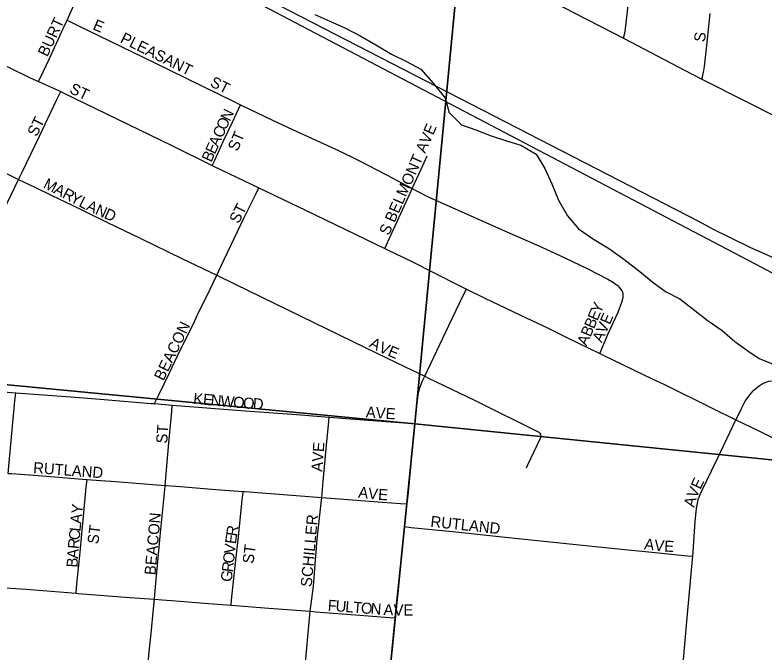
# Model space of a CAD drawing. Extents: x -209 to 4852, y 0 to 905.
# Drawn here: x 140.68 to 153.48, y 247.81 to 258.69 of the extents above; entities that cross this region are included whole.
import ezdxf

# ---------------------------------------------------------------- set-up
doc = ezdxf.new("R2010")
doc.units = 0
for name, color, linetype in [('GM_X_Airport_Location_Class_2', 7, 'Continuous'), ('GM_X_Airport_Location_Class_3', 7, 'Continuous'), ('GM_X_County_Road', 7, 'Continuous'), ('GM_X_Minor_River', 7, 'Continuous'), ('GM_X_US_Route', 7, 'Continuous')]:
    doc.layers.add(name, color=color, linetype=linetype)

msp = doc.modelspace()

# ---------------------------------------------------------------- linework, layer by layer
at = {"layer": 'GM_X_Airport_Location_Class_2'}
for points in [[(141.572, 258.596), (141.712, 258.903), (142.113, 259.746), (142.271, 260.083), (142.485, 260.53), (142.766, 261.143), (143.078, 261.826), (143.253, 262.232), (143.279, 262.293)], [(149.963, 258.863), (150.214, 258.736), (150.91, 258.379), (151.076, 258.293)], [(151.076, 258.293), (151.093, 258.351), (151.106, 258.41), (151.113, 258.453), (151.156, 258.85)], [(152.416, 257.593), (152.425, 257.631), (152.451, 257.738), (152.463, 257.808), (152.5, 258.163), (152.556, 258.713)], [(141.087, 257.55), (141.173, 257.727), (141.27, 257.944), (141.508, 258.457), (141.572, 258.596)], [(141.572, 258.596), (141.678, 258.547), (141.735, 258.521), (143.074, 257.869), (144.412, 257.215), (144.536, 257.154)], [(151.076, 258.293), (152.24, 257.682), (152.416, 257.593)], [(140.15, 258.002), (140.943, 257.616), (141.087, 257.55)], [(141.087, 257.55), (141.465, 257.38)], [(152.416, 257.593), (153.161, 257.216), (153.667, 256.96)], [(140.746, 255.878), (140.805, 256.002), (141.101, 256.618), (141.395, 257.234), (141.465, 257.38)], [(141.465, 257.38), (141.508, 257.36), (143.352, 256.463), (144.051, 256.116)], [(144.051, 256.116), (144.094, 256.208), (144.253, 256.548), (144.39, 256.843), (144.536, 257.154)], [(144.536, 257.154), (145.082, 256.89), (145.423, 256.733), (146.209, 256.374), (146.543, 256.209), (147.038, 255.951), (147.468, 255.722)], [(139.444, 256.51), (139.801, 256.339), (140.358, 256.065), (140.638, 255.93), (140.746, 255.878)], [(147.468, 255.722), (147.62, 256.052), (147.725, 256.279)], [(144.051, 256.116), (144.075, 256.104), (144.469, 255.918), (144.85, 255.736)], [(140.085, 254.51), (140.332, 255.023), (140.381, 255.13), (140.485, 255.34), (140.618, 255.613), (140.746, 255.878)], [(140.746, 255.878), (141.031, 255.742), (141.312, 255.607), (141.647, 255.444), (141.872, 255.337), (142.262, 255.146), (142.821, 254.874), (143.547, 254.523), (144.131, 254.242)], [(144.131, 254.242), (144.202, 254.391), (144.6, 255.226), (144.792, 255.617), (144.85, 255.736)], [(144.85, 255.736), (145.647, 255.356), (146.998, 254.699)], [(146.998, 254.699), (147.028, 254.763), (147.08, 254.875), (147.433, 255.646), (147.468, 255.722)], [(147.468, 255.722), (147.531, 255.688), (147.753, 255.578), (148.148, 255.398), (148.942, 255.046), (149.68, 254.721), (150.074, 254.54), (150.466, 254.353), (150.797, 254.183), (150.807, 254.178), (150.904, 254.121), (150.929, 254.104), (150.954, 254.085), (150.979, 254.066), (151.002, 254.044)], [(146.998, 254.699), (147.044, 254.677), (147.436, 254.487), (148.269, 254.068), (148.393, 254.006)], [(143.065, 252.051), (143.077, 252.074), (143.14, 252.199), (143.321, 252.577), (143.506, 252.964), (143.726, 253.403), (143.803, 253.566), (144.015, 254.004), (144.131, 254.242)], [(144.131, 254.242), (144.445, 254.092), (145.341, 253.654), (146.455, 253.11), (146.85, 252.918), (147.348, 252.679), (147.681, 252.519)], [(147.681, 252.519), (148.094, 253.387), (148.345, 253.906), (148.393, 254.006)], [(148.393, 254.006), (148.709, 253.85), (149.414, 253.516), (149.78, 253.343), (150.107, 253.181), (150.67, 252.906)], [(150.67, 252.906), (150.705, 252.987), (150.805, 253.22), (150.907, 253.443), (150.984, 253.615), (151.048, 253.785), (151.058, 253.818), (151.066, 253.843), (151.07, 253.865), (151.07, 253.875), (151.072, 253.886), (151.072, 253.901), (151.07, 253.926), (151.063, 253.953), (151.052, 253.979), (151.038, 254.002), (151.028, 254.017), (151.002, 254.044)], [(150.67, 252.906), (150.728, 252.878), (151.58, 252.468), (151.777, 252.376), (152.603, 251.968), (152.998, 251.774)], [(147.517, 251.705), (147.548, 252.012), (147.569, 252.198), (147.581, 252.257), (147.599, 252.322), (147.642, 252.438), (147.681, 252.519)], [(147.681, 252.519), (147.747, 252.487), (148.532, 252.108), (149.629, 251.563), (149.635, 251.559), (149.639, 251.556), (149.65, 251.547), (149.662, 251.528)], [(152.998, 251.774), (153.039, 251.859), (153.092, 251.969), (153.148, 252.079), (153.181, 252.13), (153.257, 252.227), (153.299, 252.272), (153.344, 252.314), (153.393, 252.352), (153.444, 252.386), (153.499, 252.414), (153.557, 252.433), (153.618, 252.441), (153.679, 252.438), (153.74, 252.43)], [(139.052, 252.363), (139.608, 252.32), (140.696, 252.237)], [(140.566, 250.86), (140.683, 252.099), (140.696, 252.237)], [(140.696, 252.237), (141.093, 252.207), (141.713, 252.159), (142.208, 252.119), (143.012, 252.055), (143.065, 252.051)], [(143.065, 252.051), (143.37, 252.027)], [(143.246, 250.655), (143.31, 251.383), (143.354, 251.855), (143.368, 252.006), (143.37, 252.027)], [(143.37, 252.027), (144.622, 251.93), (145.489, 251.866), (146.051, 251.82)], [(145.922, 250.448), (145.947, 250.722), (146.004, 251.341), (146.04, 251.689), (146.051, 251.82)], [(146.051, 251.82), (146.416, 251.79), (147.406, 251.714), (147.517, 251.705)], [(147.381, 250.338), (147.402, 250.532), (147.486, 251.399), (147.517, 251.705)], [(152.259, 249.445), (152.264, 249.514), (152.302, 250.044), (152.323, 250.255), (152.339, 250.35), (152.347, 250.386), (152.354, 250.413), (152.386, 250.5), (152.414, 250.563), (152.578, 250.903), (152.686, 251.125), (152.998, 251.774)], [(152.998, 251.774), (153.376, 251.589), (154.044, 251.262), (154.213, 251.184), (154.371, 251.114), (154.536, 251.038), (154.866, 250.875), (155.14, 250.74), (155.248, 250.689), (155.364, 250.632), (155.622, 250.506), (155.907, 250.366), (156.119, 250.263), (156.505, 250.077), (156.901, 249.887), (157.469, 249.616), (157.942, 249.381), (158.095, 249.304)], [(149.418, 250.953), (149.445, 251.006), (149.659, 251.459), (149.662, 251.466), (149.665, 251.473), (149.667, 251.482), (149.669, 251.499), (149.662, 251.528)], [(140.566, 250.86), (140.577, 250.859), (140.626, 250.856), (141.007, 250.828), (141.366, 250.799), (141.903, 250.756), (141.914, 250.755)], [(141.728, 248.812), (141.729, 248.823), (141.742, 248.965), (141.795, 249.515), (141.852, 250.131), (141.901, 250.622), (141.914, 250.755)], [(141.914, 250.755), (142.145, 250.738), (142.325, 250.724), (142.686, 250.699), (143.246, 250.655)], [(143.065, 248.71), (143.08, 248.859), (143.164, 249.785), (143.24, 250.585), (143.246, 250.655)], [(143.246, 250.655), (143.274, 250.653), (143.508, 250.634), (144.114, 250.586), (144.579, 250.551)], [(144.373, 248.608), (144.375, 248.629), (144.388, 248.75), (144.458, 249.384), (144.494, 249.726), (144.565, 250.402), (144.578, 250.538), (144.579, 250.551)], [(144.579, 250.551), (144.607, 250.549), (145.412, 250.488), (145.922, 250.448)], [(145.725, 248.504), (145.78, 248.93), (145.808, 249.301), (145.844, 249.734), (145.913, 250.351), (145.922, 250.448)], [(145.922, 250.448), (146.154, 250.43), (146.958, 250.368), (147.267, 250.346), (147.381, 250.338)], [(147.339, 249.95), (147.381, 250.338)], [(147.176, 248.393), (147.187, 248.51), (147.295, 249.55), (147.339, 249.95)], [(147.339, 249.95), (147.452, 249.938), (148.211, 249.86), (148.894, 249.789), (149.388, 249.736), (149.883, 249.685), (150.872, 249.583), (151.677, 249.503), (152.172, 249.453), (152.259, 249.445)], [(152.003, 246.542), (152.008, 246.598), (152.021, 246.764), (152.055, 247.156), (152.16, 248.33), (152.24, 249.204), (152.259, 249.445)], [(140.384, 248.918), (140.521, 248.905), (140.874, 248.88), (141.728, 248.812)], [(141.728, 248.812), (141.762, 248.809), (142.646, 248.739), (143.065, 248.71)], [(142.935, 247.375), (142.947, 247.502), (142.976, 247.811), (143.013, 248.181), (143.043, 248.489), (143.065, 248.71)], [(143.065, 248.71), (143.197, 248.7), (143.503, 248.676), (143.99, 248.637), (144.373, 248.608)], [(144.373, 248.608), (145.017, 248.558), (145.725, 248.504)], [(145.605, 247.164), (145.614, 247.263), (145.677, 248.003), (145.725, 248.504)], [(145.725, 248.504), (145.821, 248.497), (146.5, 248.443), (147.082, 248.4), (147.176, 248.393)], [(147.05, 247.048), (147.052, 247.072), (147.063, 247.186), (147.094, 247.522), (147.176, 248.393)]]:
    msp.add_lwpolyline(points, dxfattribs=at)
at = {"layer": 'GM_X_County_Road'}
for points in [[(145.805, 258.695), (146.062, 258.58), (146.326, 258.464), (146.589, 258.325), (146.845, 258.179), (147.117, 258.018), (147.373, 257.895), (147.614, 257.764), (147.824, 257.52), (148.034, 257.26), (148.093, 257.025), (148.31, 256.811), (148.552, 256.726), (148.816, 256.625), (149.08, 256.54), (149.321, 256.462)], [(149.321, 256.462), (149.585, 256.308), (149.735, 256.064), (149.854, 255.806), (149.965, 255.524), (150.122, 255.258), (150.309, 255.036), (150.565, 254.86), (150.836, 254.691), (151.085, 254.515), (151.386, 254.285), (151.581, 254.117), (151.792, 253.964), (152.041, 253.84), (152.296, 253.641), (152.507, 253.473), (152.763, 253.297), (152.981, 253.113), (153.199, 252.952), (153.395, 252.822), (153.659, 252.714)]]:
    msp.add_lwpolyline(points, dxfattribs=at)
at = {"layer": 'GM_X_Minor_River'}
for points in [[(129.104, 273.545), (149.411, 271.455), (147.511, 251.706), (127.195, 253.652)], [(149.411, 271.455), (170.498, 269.384), (168.839, 249.556), (147.511, 251.706)], [(147.511, 251.706), (145.448, 231.165), (125.307, 233.161), (127.195, 253.652)], [(147.511, 251.706), (168.839, 249.556), (166.746, 229.007), (145.448, 231.165)]]:
    msp.add_lwpolyline(points, close=True, dxfattribs=at)
at = {"layer": 'GM_X_US_Route'}
for points in [[(129.972, 266.728), (130.129, 266.605), (153.543, 254.322), (153.942, 254.104), (154.418, 253.763), (155.17, 253.142), (156.822, 251.783), (158.293, 250.567), (160.821, 248.573)], [(129.972, 266.728), (130.962, 266.216), (133.305, 265.008), (133.688, 264.804), (134.402, 264.442), (134.516, 264.383), (135.007, 264.13), (135.435, 263.906), (135.725, 263.759), (135.937, 263.652), (136.126, 263.553), (136.724, 263.23), (137.065, 263.056), (137.379, 262.892), (137.691, 262.73), (138.428, 262.347), (139.837, 261.626), (140.928, 261.062), (142.687, 260.151), (143.202, 259.885), (144.594, 259.166), (152.355, 255.164), (152.596, 255.034)], [(152.596, 255.034), (153.245, 254.714), (154.044, 254.362), (154.498, 254.175), (155.336, 253.855), (156.129, 253.6), (156.72, 253.426), (157.431, 253.24), (157.955, 253.122), (158.425, 253.021), (158.811, 252.951), (159.587, 252.826), (160.098, 252.759), (160.791, 252.686), (161.76, 252.584), (162.954, 252.458), (163.495, 252.4), (164.146, 252.331), (164.967, 252.247)]]:
    msp.add_lwpolyline(points, dxfattribs=at)

# ---------------------------------------------------------------- texts
at = {"layer": 'GM_X_Airport_Location_Class_3'}
for s, height, rotation, p in [('BURT', 0.1894, 64.8007, (141.236, 257.961)), ('E', 0.189, 336.7995, (141.999, 258.446)), ('PLEASANT', 0.1894, 333.7496, (142.468, 258.228)), ('S', 0.189, 82.8783, (152.466, 258.217)), ('ST', 0.1894, 333.435, (144.001, 257.478)), ('ST', 0.1894, 334.9879, (141.6, 257.362)), ('N', 0.189, 63.8553, (144.352, 256.858)), ('ST', 0.1894, 63.4349, (141.053, 256.596)), ('O', 0.189, 65.3561, (144.283, 256.707)), ('C', 0.189, 65.6405, (144.222, 256.571)), ('S BELMONT AVE', 0.18939, 66.1925, (147.069, 254.911)), ('ST', 0.1894, 66.7995, (144.485, 256.349)), ('E', 0.189, 65.6408, (144.098, 256.298)), ('A', 0.189, 65.6447, (144.153, 256.419)), ('B', 0.189, 65.6455, (144.036, 256.161)), ('M', 0.189, 332.4247, (141.152, 255.744)), ('A', 0.189, 332.4377, (141.329, 255.652)), ('R', 0.189, 332.4247, (141.477, 255.575)), ('Y', 0.189, 332.4377, (141.61, 255.505)), ('L', 0.189, 332.9618, (141.759, 255.427)), ('A', 0.189, 335.2294, (141.885, 255.363)), ('N', 0.189, 335.8473, (142.038, 255.292)), ('D', 0.189, 335.85, (142.191, 255.224)), ('ST', 0.1894, 63.4349, (144.503, 255.112)), ('Y', 0.189, 65.5759, (150.682, 253.575)), ('E', 0.189, 67.0113, (150.63, 253.453)), ('E', 0.189, 66.8167, (150.843, 253.388)), ('BEACON', 0.1894, 64.3252, (143.22, 252.428)), ('B', 0.189, 67.015, (150.572, 253.315)), ('V', 0.189, 65.723, (150.773, 253.232)), ('B', 0.189, 67.0214, (150.513, 253.177)), ('A', 0.189, 67.0296, (150.448, 253.024)), ('A', 0.189, 65.5759, (150.704, 253.08)), ('A', 0.189, 331.988, (146.72, 253.027)), ('V', 0.189, 336.3291, (146.881, 252.942)), ('E', 0.189, 337.1667, (147.037, 252.874)), ('K', 0.189, 354.7244, (143.722, 252.048)), ('E', 0.189, 354.719, (143.888, 252.033)), ('N', 0.189, 354.7244, (144.02, 252.021)), ('W', 0.189, 354.7211, (144.186, 252.005)), ('O', 0.189, 354.778, (144.402, 251.986)), ('O', 0.189, 356.0857, (144.573, 251.97)), ('D', 0.189, 356.801, (144.742, 251.958)), ('AVE', 0.1894, 356.0531, (146.671, 251.815)), ('ST', 0.1894, 86.4258, (143.283, 251.365)), ('AVE', 0.1894, 85.9088, (145.933, 250.882)), ('RUTLAND', 0.1894, 355.6694, (140.989, 250.865)), ('E', 0.189, 64.6447, (152.389, 250.574)), ('V', 0.189, 66.6479, (152.323, 250.423)), ('A', 0.189, 353.3738, (146.54, 250.448)), ('V', 0.189, 353.3844, (146.705, 250.429)), ('E', 0.189, 355.848, (146.88, 250.409)), ('A', 0.189, 75.1685, (152.283, 250.269)), ('Y', 0.189, 84.2823, (141.831, 250.16)), ('A', 0.189, 84.2763, (141.814, 249.994)), ('BEACON', 0.1894, 84.9895, (143.083, 249.116)), ('SCHILLER', 0.1894, 84.8807, (145.75, 248.915)), ('RUTLAND', 0.1894, 353.9451, (147.773, 249.948)), ('L', 0.189, 84.2799, (141.801, 249.861)), ('C', 0.189, 84.2834, (141.786, 249.712)), ('ST', 0.1894, 82.8657, (142.106, 249.644)), ('R', 0.189, 81.468, (144.474, 249.777)), ('R', 0.189, 84.4537, (141.771, 249.563)), ('E', 0.189, 82.631, (144.457, 249.645)), ('A', 0.189, 352.5036, (151.423, 249.565)), ('V', 0.189, 83.4975, (144.438, 249.48)), ('ST', 0.1894, 82.8649, (144.756, 249.31)), ('V', 0.189, 354.3893, (151.595, 249.542)), ('E', 0.189, 356.1136, (151.767, 249.526)), ('A', 0.189, 85.7337, (141.759, 249.398)), ('O', 0.189, 83.4975, (144.419, 249.315)), ('B', 0.189, 86.3547, (141.75, 249.248)), ('R', 0.189, 83.5003, (144.402, 249.166)), ('G', 0.189, 83.4945, (144.383, 249)), ('F', 0.189, 355.5562, (146.021, 248.515)), ('U', 0.189, 355.5448, (146.154, 248.505)), ('L', 0.189, 355.5578, (146.32, 248.492)), ('T', 0.189, 355.5562, (146.453, 248.482)), ('O', 0.189, 355.5448, (146.586, 248.471)), ('N', 0.189, 355.5594, (146.752, 248.458)), ('A', 0.189, 357.0991, (146.974, 248.441)), ('V', 0.189, 359.8295, (147.15, 248.432)), ('E', 0.189, 359.9956, (147.318, 248.432))]:
    msp.add_text(s, height=height, rotation=rotation, dxfattribs=at).set_placement(p)

doc.saveas('drawing.dxf')
